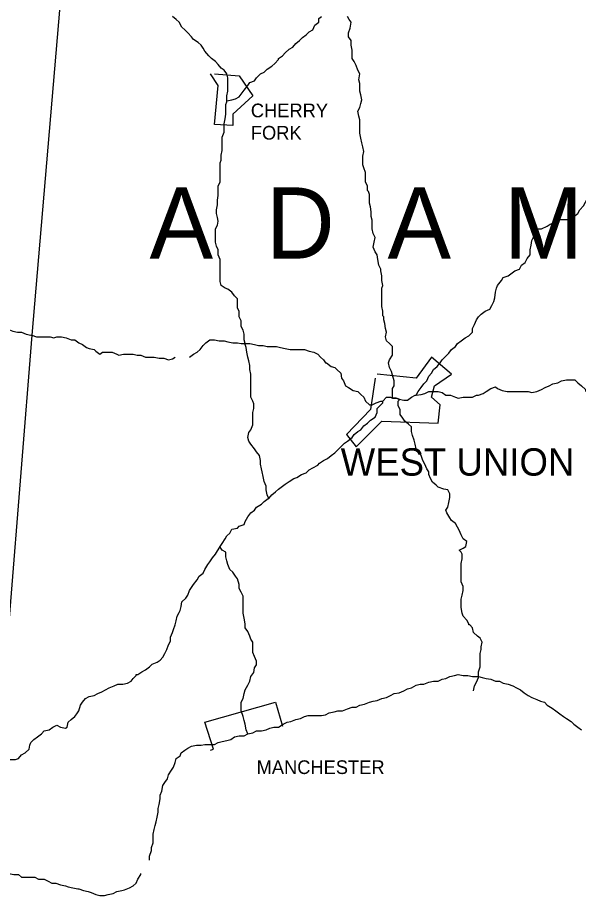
# Model space of a CAD drawing. Extents: x 0 to 40.2, y 0 to 22.
# Drawn here: x 3.548 to 4.348, y 15.986 to 17.238 of the extents above; entities that cross this region are included whole.
import ezdxf

# ---------------------------------------------------------------- set-up
doc = ezdxf.new("R2010")
doc.units = 0
doc.layers.add('Default', color=7, linetype='Continuous')
doc.layers.add('TR_Turning_Path1', color=7, linetype='Continuous')

msp = doc.modelspace()

# ---------------------------------------------------------------- linework, layer by layer
at = {"layer": 'Default'}
for points in [[(3.6488, 17.7215), (3.6215, 17.4107), (3.5684, 16.7848), (3.5206, 16.1972), (3.5111, 16.0241), (3.5097, 16.0009)], [(3.8465, 17.1189), (3.8465, 17.1257), (3.8479, 17.1325), (3.8479, 17.138), (3.8479, 17.1448), (3.8479, 17.1516), (3.8465, 17.1571), (3.8424, 17.1625), (3.8383, 17.1652), (3.8342, 17.1707), (3.8301, 17.1748), (3.8247, 17.1789), (3.8206, 17.183), (3.8151, 17.1898), (3.8124, 17.1939), (3.8097, 17.198), (3.8056, 17.2021), (3.7988, 17.2061), (3.796, 17.2102), (3.7906, 17.2157), (3.7865, 17.2198), (3.7824, 17.2239), (3.7783, 17.2307), (3.7742, 17.2348), (3.7688, 17.2389)], [(3.9201, 17.1789), (3.9256, 17.183), (3.9297, 17.1871), (3.9351, 17.1925), (3.9406, 17.1952), (3.9447, 17.2007), (3.9501, 17.2048), (3.9542, 17.2089), (3.9597, 17.213), (3.9638, 17.2171), (3.9692, 17.2198), (3.9719, 17.2266), (3.9774, 17.2307), (3.9774, 17.2361), (3.9815, 17.2389)], [(4.036, 17.0916), (4.0346, 17.0971), (4.0333, 17.1039), (4.036, 17.1093), (4.0374, 17.1148), (4.0387, 17.1202), (4.0374, 17.1271), (4.036, 17.1325), (4.036, 17.138), (4.036, 17.1434), (4.0346, 17.1489), (4.036, 17.1571), (4.0333, 17.1625), (4.0306, 17.1693), (4.0278, 17.1748), (4.0251, 17.1789), (4.0251, 17.1857), (4.0251, 17.1911), (4.0237, 17.198), (4.0237, 17.2048), (4.0197, 17.2102), (4.0197, 17.2157), (4.0224, 17.2225), (4.0237, 17.2307), (4.021, 17.2348), (4.0183, 17.2389)], [(3.8465, 17.1189), (3.8533, 17.1202), (3.8588, 17.1216), (3.8642, 17.1243), (3.8669, 17.1284), (3.871, 17.1339), (3.8765, 17.1407), (3.8792, 17.1448), (3.886, 17.1475), (3.8888, 17.1516), (3.8942, 17.1571), (3.8997, 17.1598), (3.9038, 17.1639), (3.9106, 17.168), (3.9147, 17.1721), (3.9201, 17.1775), (3.9201, 17.1789)], [(3.8288, 17.1571), (3.8642, 17.1543), (3.8833, 17.1257), (3.8547, 17.0998), (3.8547, 17.0834), (3.8288, 17.0848), (3.8342, 17.1407), (3.8233, 17.1571)], [(3.8301, 16.9362), (3.8329, 16.9416), (3.8342, 16.9471), (3.8329, 16.9525), (3.8315, 16.958), (3.8315, 16.9635), (3.8329, 16.9703), (3.8329, 16.9771), (3.8342, 16.9839), (3.8342, 16.9907), (3.8342, 16.9975), (3.837, 17.003), (3.837, 17.0098), (3.837, 17.0166), (3.837, 17.0234), (3.837, 17.0303), (3.8383, 17.0344), (3.8383, 17.0412), (3.8397, 17.048), (3.8397, 17.0548), (3.8397, 17.0603), (3.8397, 17.0671), (3.8424, 17.0739), (3.8424, 17.0807), (3.8424, 17.0862), (3.8438, 17.093), (3.8451, 17.0998), (3.8451, 17.1052), (3.8451, 17.1134), (3.8465, 17.1175), (3.8465, 17.1189)], [(4.0469, 16.9907), (4.0469, 16.9975), (4.0442, 17.003), (4.0442, 17.0098), (4.0442, 17.0166), (4.0415, 17.0234), (4.0401, 17.0275), (4.0401, 17.0344), (4.0401, 17.0398), (4.0415, 17.0466), (4.0401, 17.0534), (4.0387, 17.0589), (4.0374, 17.0657), (4.036, 17.0725), (4.036, 17.078), (4.036, 17.0848), (4.036, 17.0903), (4.036, 17.0903), (4.036, 17.0916)], [(4.3114, 16.9444), (4.3182, 16.9485), (4.3223, 16.9498), (4.3305, 16.9498), (4.336, 16.9498), (4.3414, 16.9539), (4.3469, 16.958), (4.3496, 16.9635), (4.3551, 16.9689), (4.3578, 16.9744), (4.3605, 16.9798), (4.3632, 16.9853), (4.3687, 16.9894), (4.3728, 16.9934), (4.3769, 16.9989), (4.3796, 17.0057), (4.3837, 17.0098), (4.3878, 17.0153), (4.3919, 17.0207), (4.3919, 17.0248)], [(4.066, 16.8789), (4.0633, 16.8844), (4.0619, 16.8926), (4.0606, 16.8994), (4.0578, 16.9035), (4.0551, 16.9103), (4.0565, 16.9171), (4.0578, 16.9239), (4.0551, 16.9294), (4.0537, 16.9362), (4.0537, 16.9416), (4.0537, 16.9485), (4.0524, 16.9539), (4.0524, 16.9607), (4.051, 16.9675), (4.0496, 16.973), (4.0496, 16.9798), (4.0496, 16.9853), (4.0483, 16.9894), (4.0469, 16.9907)], [(3.8724, 16.7726), (3.871, 16.778), (3.871, 16.7862), (3.8697, 16.7917), (3.8669, 16.7971), (3.8669, 16.8053), (3.8642, 16.8108), (3.8642, 16.8189), (3.8615, 16.823), (3.8615, 16.8298), (3.8615, 16.8367), (3.8574, 16.8407), (3.8533, 16.8462), (3.8479, 16.8503), (3.8438, 16.8517), (3.8383, 16.8557), (3.837, 16.8612), (3.837, 16.868), (3.837, 16.8748), (3.837, 16.8803), (3.837, 16.8871), (3.837, 16.8926), (3.8342, 16.8994), (3.8342, 16.9062), (3.8315, 16.9116), (3.8301, 16.9171), (3.8301, 16.9239), (3.8301, 16.9307), (3.8301, 16.9348), (3.8301, 16.9362)], [(4.2787, 16.9062), (4.2801, 16.913), (4.2814, 16.9198), (4.2842, 16.9253), (4.2869, 16.9307), (4.2896, 16.9362), (4.2951, 16.9362), (4.3032, 16.9403), (4.3073, 16.943), (4.3114, 16.9444), (4.3114, 16.9444)], [(4.2146, 16.8189), (4.2214, 16.8217), (4.2242, 16.8271), (4.2269, 16.8326), (4.2283, 16.838), (4.2296, 16.8462), (4.231, 16.8517), (4.2323, 16.8557), (4.2378, 16.8626), (4.2405, 16.8667), (4.2473, 16.8694), (4.2514, 16.8721), (4.2569, 16.8762), (4.2637, 16.8789), (4.2664, 16.8844), (4.2719, 16.8885), (4.2746, 16.8939), (4.2787, 16.8994), (4.2787, 16.9048), (4.2787, 16.9062), (4.2787, 16.9062)], [(4.0687, 16.8121), (4.0687, 16.8189), (4.0674, 16.8257), (4.0674, 16.8326), (4.0674, 16.838), (4.0674, 16.8435), (4.0674, 16.8517), (4.0687, 16.8557), (4.0674, 16.8626), (4.0674, 16.8694), (4.066, 16.8762), (4.066, 16.8789), (4.066, 16.8789)], [(3.4797, 16.8135), (3.4866, 16.8094), (3.4934, 16.8067), (3.4988, 16.8026), (3.5043, 16.8026), (3.5097, 16.7998), (3.5165, 16.7971), (3.522, 16.7958), (3.5288, 16.7944), (3.5343, 16.793), (3.5411, 16.7903), (3.5479, 16.7889), (3.5534, 16.7889), (3.5602, 16.7862), (3.567, 16.7848), (3.5684, 16.7848)], [(4.0824, 16.6949), (4.0824, 16.7017), (4.0824, 16.7085), (4.0851, 16.7126), (4.0851, 16.7194), (4.0824, 16.7276), (4.081, 16.733), (4.0783, 16.7385), (4.0769, 16.7453), (4.0783, 16.7494), (4.0824, 16.7562), (4.0824, 16.7617), (4.0824, 16.7685), (4.0783, 16.7726), (4.0742, 16.7767), (4.0728, 16.7821), (4.0742, 16.7889), (4.0728, 16.7944), (4.0715, 16.8012), (4.0701, 16.8067), (4.0701, 16.8108), (4.0687, 16.8121)], [(4.1165, 16.699), (4.1192, 16.7044), (4.1233, 16.7099), (4.1274, 16.7153), (4.1315, 16.7194), (4.1342, 16.7262), (4.1383, 16.7303), (4.141, 16.7358), (4.1464, 16.7399), (4.1505, 16.7453), (4.1533, 16.7494), (4.1574, 16.7535), (4.1628, 16.7589), (4.1669, 16.7644), (4.1724, 16.7685), (4.1751, 16.7726), (4.1805, 16.7767), (4.186, 16.7808), (4.1914, 16.7835), (4.1969, 16.7889), (4.1969, 16.7944), (4.1996, 16.7998), (4.2023, 16.8067), (4.2051, 16.8108), (4.2092, 16.8148), (4.2146, 16.8189), (4.2146, 16.8189), (4.2146, 16.8189)], [(3.5684, 16.7848), (3.5752, 16.7821), (3.5806, 16.7821), (3.5874, 16.7821), (3.5943, 16.7821), (3.5997, 16.7808), (3.6038, 16.7821), (3.6106, 16.7821), (3.6174, 16.7808), (3.6243, 16.778), (3.6297, 16.778), (3.6352, 16.7739), (3.6406, 16.7712), (3.6461, 16.7671), (3.6502, 16.7658), (3.657, 16.7644), (3.6597, 16.7617), (3.6652, 16.7576), (3.6693, 16.7603), (3.6761, 16.7603), (3.6829, 16.7603), (3.6897, 16.7576), (3.6924, 16.7562)], [(3.7933, 16.7535), (3.7988, 16.7576), (3.8042, 16.7603), (3.8083, 16.7644), (3.8124, 16.7698), (3.8165, 16.7739), (3.822, 16.778), (3.8288, 16.778), (3.8356, 16.7767), (3.8424, 16.7767), (3.8479, 16.7753), (3.8547, 16.7739), (3.8615, 16.7739), (3.8669, 16.7726), (3.871, 16.7726), (3.8724, 16.7726)], [(3.8833, 16.6662), (3.8833, 16.6744), (3.8847, 16.6799), (3.8847, 16.6867), (3.8833, 16.6908), (3.8806, 16.6962), (3.8806, 16.7044), (3.8806, 16.7099), (3.8806, 16.7167), (3.8806, 16.7235), (3.8806, 16.7289), (3.8792, 16.7358), (3.8792, 16.7412), (3.8779, 16.748), (3.8765, 16.7535), (3.8751, 16.7603), (3.8738, 16.7671), (3.8724, 16.7712), (3.8724, 16.7726)], [(3.8724, 16.7726), (3.8792, 16.7726), (3.886, 16.7712), (3.8915, 16.7698), (3.8983, 16.7698), (3.9038, 16.7685), (3.9119, 16.7685), (3.9174, 16.7685), (3.9228, 16.7671), (3.9297, 16.7658), (3.9365, 16.7644), (3.9433, 16.7644), (3.9501, 16.7644), (3.9569, 16.7644), (3.9569, 16.7644)], [(3.9569, 16.7644), (3.9638, 16.7617), (3.9706, 16.7603), (3.976, 16.7576), (3.9801, 16.7535), (3.9842, 16.7494), (3.9869, 16.7453), (3.9883, 16.7453)], [(3.6924, 16.7562), (3.6992, 16.7576), (3.7061, 16.7576), (3.7129, 16.7576), (3.7183, 16.7562), (3.7238, 16.7562), (3.7306, 16.7535), (3.7388, 16.7535), (3.7429, 16.7535), (3.7497, 16.7521), (3.7565, 16.7521), (3.7633, 16.7494), (3.7688, 16.7508), (3.7729, 16.7535), (3.7729, 16.7535)], [(4.0578, 16.7235), (4.051, 16.6785), (4.0169, 16.6431), (4.0306, 16.6253), (4.0674, 16.6621), (4.1478, 16.6594), (4.1505, 16.6853), (4.1383, 16.6962), (4.1424, 16.7126), (4.1669, 16.7289), (4.1383, 16.7535), (4.1165, 16.7235), (4.0606, 16.7289)], [(3.9883, 16.7453), (3.9951, 16.7399), (4.0006, 16.7385), (4.0033, 16.7358), (4.0087, 16.7303), (4.0101, 16.7235), (4.0128, 16.7194), (4.0156, 16.7126), (4.0197, 16.7099), (4.0265, 16.7058), (4.0333, 16.7044), (4.0374, 16.7003), (4.0415, 16.6962), (4.0442, 16.6908), (4.0496, 16.6853), (4.0537, 16.6853), (4.0592, 16.688), (4.066, 16.6908), (4.0687, 16.6908)], [(4.2051, 16.699), (4.2119, 16.7017), (4.216, 16.7044), (4.2228, 16.7085), (4.2296, 16.7112), (4.2323, 16.7085), (4.2392, 16.7058), (4.246, 16.7044), (4.2514, 16.7044), (4.2569, 16.7044)], [(4.2569, 16.7044), (4.2623, 16.7044), (4.2705, 16.7044), (4.276, 16.7044), (4.2814, 16.703), (4.2882, 16.7044), (4.2951, 16.7071), (4.3005, 16.7099), (4.306, 16.7126), (4.3114, 16.7153), (4.3182, 16.7167), (4.3237, 16.7194), (4.3305, 16.7208), (4.3373, 16.7208), (4.3428, 16.7208), (4.3469, 16.7167), (4.3523, 16.7126), (4.3578, 16.7071), (4.3578, 16.7044)], [(4.0919, 16.6935), (4.0987, 16.6921), (4.1042, 16.6921), (4.1096, 16.6962), (4.1151, 16.699), (4.1165, 16.699)], [(4.0919, 16.6935), (4.0987, 16.6921), (4.1042, 16.6921), (4.1096, 16.6962), (4.1151, 16.699), (4.1165, 16.699)], [(4.1165, 16.699), (4.1233, 16.7003), (4.1287, 16.7017), (4.1342, 16.7044), (4.141, 16.7044), (4.1478, 16.7044), (4.1533, 16.703), (4.1587, 16.699), (4.1655, 16.699), (4.1724, 16.6962), (4.1764, 16.6949), (4.1833, 16.6962), (4.1901, 16.6962), (4.1969, 16.6962), (4.2023, 16.699), (4.2051, 16.699), (4.2051, 16.699)], [(3.9065, 16.5517), (3.9106, 16.5572), (3.916, 16.5612), (3.9201, 16.5653), (3.9256, 16.5694), (3.9297, 16.5722), (3.9351, 16.5762), (3.9419, 16.5803), (3.946, 16.5817), (3.9528, 16.5858), (3.9597, 16.5885), (3.9638, 16.5926), (3.9692, 16.5953), (3.976, 16.5994), (3.9787, 16.6021), (3.9842, 16.6062), (3.9897, 16.609), (3.9951, 16.6131), (4.0006, 16.6171), (4.0047, 16.6212), (4.0087, 16.6253), (4.0142, 16.6308), (4.0183, 16.6335), (4.0251, 16.639), (4.0278, 16.6431), (4.0333, 16.6471), (4.0374, 16.6499), (4.0415, 16.6553), (4.0469, 16.6594), (4.051, 16.6635), (4.0578, 16.6676), (4.0606, 16.6744), (4.0606, 16.6799), (4.0646, 16.684), (4.0687, 16.688), (4.0687, 16.6908), (4.0687, 16.6908)], [(4.0687, 16.6908), (4.0742, 16.6962), (4.0796, 16.6962), (4.0824, 16.6949)], [(4.0687, 16.6908), (4.0742, 16.6962), (4.0796, 16.6962), (4.0824, 16.6949)], [(4.0824, 16.6949), (4.0878, 16.6949), (4.0919, 16.6935)], [(4.0824, 16.6949), (4.0878, 16.6949), (4.0919, 16.6935)], [(4.0919, 16.6935), (4.0878, 16.6949), (4.0824, 16.6949)], [(4.1342, 16.5899), (4.1315, 16.594), (4.1287, 16.6008), (4.126, 16.6062), (4.1233, 16.6131), (4.1192, 16.6171), (4.1165, 16.6226), (4.1151, 16.6294), (4.1137, 16.6349), (4.111, 16.6417), (4.1096, 16.6471), (4.1096, 16.654), (4.1055, 16.658), (4.1001, 16.6621), (4.0974, 16.6662), (4.0933, 16.6717), (4.0933, 16.6785), (4.0905, 16.684), (4.0905, 16.6908), (4.0919, 16.6921), (4.0919, 16.6935)], [(3.9065, 16.5517), (3.9038, 16.5572), (3.9024, 16.564), (3.9024, 16.5694), (3.8997, 16.5762), (3.8983, 16.5831), (3.8969, 16.5899), (3.8956, 16.594), (3.8942, 16.6008), (3.8942, 16.6062), (3.8929, 16.6131), (3.8888, 16.6185), (3.886, 16.6226), (3.8806, 16.6294), (3.8779, 16.6335), (3.8765, 16.639), (3.8779, 16.6458), (3.8806, 16.6499), (3.8833, 16.6567), (3.8833, 16.6621), (3.8833, 16.6662), (3.8833, 16.6662)], [(4.1778, 16.4781), (4.1833, 16.4808), (4.1874, 16.4835), (4.1887, 16.4903), (4.1833, 16.4944), (4.1805, 16.4999), (4.1778, 16.5067), (4.1751, 16.5108), (4.1724, 16.5163), (4.1669, 16.5203), (4.1642, 16.5244), (4.1601, 16.5312), (4.1587, 16.5353), (4.1614, 16.5394), (4.1628, 16.5462), (4.1642, 16.5531), (4.1642, 16.5585), (4.1614, 16.564), (4.156, 16.5653), (4.1478, 16.5681), (4.1451, 16.5708), (4.1396, 16.5749), (4.1369, 16.5803), (4.1342, 16.5858), (4.1342, 16.5899), (4.1342, 16.5899), (4.1342, 16.5899)], [(3.837, 16.4835), (3.8397, 16.4876), (3.8438, 16.4944), (3.8465, 16.4985), (3.8506, 16.5026), (3.8533, 16.5081), (3.8615, 16.5094), (3.8642, 16.5122), (3.871, 16.5149), (3.8724, 16.519), (3.8765, 16.5258), (3.8806, 16.5312), (3.886, 16.5353), (3.8888, 16.5394), (3.8956, 16.5435), (3.8997, 16.5476), (3.9051, 16.5517), (3.9065, 16.5517)], [(3.837, 16.4835), (3.8397, 16.4876), (3.8438, 16.4944), (3.8465, 16.4985), (3.8506, 16.5026), (3.8533, 16.5081), (3.8615, 16.5094), (3.8642, 16.5122), (3.871, 16.5149), (3.8724, 16.519), (3.8765, 16.5258), (3.8806, 16.5312), (3.886, 16.5353), (3.8888, 16.5394), (3.8956, 16.5435), (3.8997, 16.5476), (3.9051, 16.5517), (3.9065, 16.5517)], [(3.7797, 16.3922), (3.7811, 16.3976), (3.7824, 16.4045), (3.7879, 16.4099), (3.7906, 16.414), (3.7933, 16.4208), (3.796, 16.4249), (3.7988, 16.429), (3.8042, 16.4358), (3.807, 16.4413), (3.8124, 16.4454), (3.8151, 16.4508), (3.8192, 16.4576), (3.822, 16.4617), (3.826, 16.4672), (3.8301, 16.4726), (3.837, 16.4835)], [(3.8765, 16.2163), (3.8738, 16.2218), (3.8724, 16.2299), (3.871, 16.2354), (3.8697, 16.2408), (3.8669, 16.249), (3.8669, 16.2545), (3.8669, 16.2613), (3.8697, 16.2667), (3.871, 16.2736), (3.8724, 16.279), (3.8765, 16.2858), (3.8792, 16.2913), (3.8806, 16.2981), (3.8847, 16.3036), (3.886, 16.3104), (3.8888, 16.3145), (3.8888, 16.3199), (3.886, 16.3267), (3.8833, 16.3322), (3.8833, 16.339), (3.8833, 16.3472), (3.8806, 16.3513), (3.8792, 16.3554), (3.8765, 16.3622), (3.8724, 16.3676), (3.8724, 16.3731), (3.871, 16.3813), (3.8697, 16.3881), (3.8697, 16.3922), (3.8697, 16.399), (3.8697, 16.4058), (3.8697, 16.4126), (3.8669, 16.4181), (3.8642, 16.4235), (3.8642, 16.429), (3.8615, 16.4372), (3.8588, 16.4413), (3.8547, 16.4467), (3.8506, 16.4508), (3.8479, 16.4576), (3.8465, 16.4631), (3.8451, 16.4685), (3.8451, 16.4753), (3.8397, 16.4781), (3.837, 16.4822), (3.837, 16.4835)], [(4.1833, 16.4208), (4.1833, 16.4263), (4.1805, 16.4331), (4.1805, 16.4372), (4.1805, 16.4426), (4.1805, 16.4467), (4.1805, 16.4535), (4.1805, 16.459), (4.1819, 16.4658), (4.1819, 16.4726), (4.1805, 16.4753), (4.1778, 16.4781)], [(4.1914, 16.3731), (4.1887, 16.3785), (4.1833, 16.384), (4.1819, 16.3881), (4.1805, 16.3963), (4.1805, 16.4017), (4.1805, 16.4085), (4.1819, 16.414), (4.1833, 16.4208), (4.1833, 16.4208)], [(3.7197, 16.3008), (3.7252, 16.3049), (3.7306, 16.3076), (3.7361, 16.3117), (3.7401, 16.3158), (3.747, 16.3186), (3.7511, 16.3213), (3.7551, 16.3254), (3.7579, 16.3308), (3.7606, 16.3363), (3.7633, 16.3431), (3.7661, 16.3486), (3.7661, 16.354), (3.7688, 16.3608), (3.7701, 16.3649), (3.7729, 16.3717), (3.7742, 16.3772), (3.7756, 16.384), (3.7783, 16.3895), (3.7797, 16.3922), (3.7797, 16.3922)], [(4.2051, 16.2981), (4.2051, 16.3049), (4.2078, 16.3117), (4.2078, 16.3172), (4.2078, 16.3226), (4.2078, 16.3308), (4.2092, 16.3363), (4.2092, 16.3404), (4.2105, 16.3472), (4.2078, 16.3526), (4.2037, 16.3554), (4.1983, 16.3608), (4.1969, 16.3676), (4.1928, 16.3717), (4.1914, 16.3717), (4.1914, 16.3731)], [(3.6188, 16.2258), (3.6202, 16.2327), (3.6243, 16.2368), (3.6297, 16.2408), (3.6324, 16.2449), (3.6352, 16.249), (3.6379, 16.2572), (3.6406, 16.2613), (3.6447, 16.2667), (3.6502, 16.2695), (3.657, 16.2708), (3.6624, 16.2736), (3.6679, 16.2763), (3.6733, 16.279), (3.6788, 16.2817), (3.6856, 16.2845), (3.6911, 16.2872), (3.6979, 16.2872), (3.7047, 16.2886), (3.7102, 16.2913), (3.7129, 16.2954), (3.717, 16.2995), (3.717, 16.3008), (3.7197, 16.3008)], [(3.8765, 16.2163), (3.8833, 16.2177), (3.8888, 16.2204), (3.8956, 16.2204), (3.9024, 16.2218), (3.9078, 16.2245), (3.9133, 16.2258), (3.9201, 16.2258), (3.9269, 16.2299), (3.9324, 16.2327), (3.9378, 16.234), (3.9447, 16.2368), (3.9515, 16.2381), (3.9569, 16.2408), (3.9624, 16.2422), (3.9678, 16.2422), (3.976, 16.2422), (3.9815, 16.2422), (3.9869, 16.2436), (3.9924, 16.2463), (3.9992, 16.2477), (4.0047, 16.249), (4.0115, 16.249), (4.0183, 16.2517), (4.0251, 16.2545), (4.0306, 16.2545), (4.036, 16.2572), (4.0428, 16.2586), (4.0496, 16.2613), (4.0551, 16.2627), (4.0606, 16.264), (4.0674, 16.2667), (4.0742, 16.2681), (4.0796, 16.2708), (4.0851, 16.2736), (4.0919, 16.2749), (4.0987, 16.2777), (4.1042, 16.2804), (4.1096, 16.2817), (4.1165, 16.2858), (4.1219, 16.2872), (4.1274, 16.2872), (4.1342, 16.2899), (4.141, 16.2913), (4.1478, 16.2913), (4.1533, 16.294), (4.1587, 16.2954), (4.1642, 16.2981), (4.171, 16.2995), (4.1764, 16.3008), (4.1833, 16.2995), (4.1901, 16.2995), (4.1969, 16.2981), (4.2023, 16.2981), (4.2037, 16.2981), (4.2051, 16.2981)], [(4.1983, 16.2777), (4.1996, 16.2845), (4.2023, 16.2899), (4.2051, 16.2967), (4.2051, 16.2981)], [(4.2051, 16.2981), (4.2105, 16.2967), (4.216, 16.2954), (4.2228, 16.294), (4.2296, 16.2913), (4.2351, 16.2913), (4.2405, 16.2886), (4.2473, 16.2872), (4.2542, 16.2845), (4.2596, 16.2817), (4.2651, 16.279), (4.2705, 16.2749), (4.276, 16.2708), (4.2814, 16.2681), (4.2882, 16.2654), (4.2937, 16.2627), (4.2992, 16.2613), (4.3032, 16.2572), (4.3101, 16.2531), (4.3155, 16.249), (4.321, 16.2449), (4.3264, 16.2408), (4.3305, 16.2381), (4.3373, 16.234), (4.3414, 16.2299), (4.3469, 16.2258), (4.3523, 16.2218)], [(3.8233, 16.1931), (3.8274, 16.1945), (3.8151, 16.2327), (3.916, 16.2613), (3.9256, 16.2272)], [(3.5206, 16.1972), (3.5206, 16.189), (3.5206, 16.1836), (3.5261, 16.1809), (3.5329, 16.1795), (3.5397, 16.1795), (3.5452, 16.1795), (3.5493, 16.1809), (3.5534, 16.1863), (3.5588, 16.189), (3.5643, 16.1945), (3.5656, 16.1999), (3.567, 16.204), (3.5711, 16.2081), (3.5765, 16.2122), (3.582, 16.2163), (3.5861, 16.2204), (3.5929, 16.2218), (3.5984, 16.2258), (3.6038, 16.2286), (3.6093, 16.2258), (3.6161, 16.2245), (3.6188, 16.2258), (3.6188, 16.2258)], [(3.7811, 16.189), (3.7865, 16.1931), (3.7906, 16.1958), (3.796, 16.1986), (3.8029, 16.1999), (3.8097, 16.1999), (3.8151, 16.2013), (3.822, 16.2013), (3.8288, 16.2013), (3.8342, 16.204), (3.8397, 16.2054), (3.8465, 16.2068), (3.8519, 16.2081), (3.8574, 16.2122), (3.8642, 16.2136), (3.871, 16.2136), (3.8765, 16.2163), (3.8765, 16.2163)], [(3.7361, 16.0363), (3.7361, 16.0418), (3.7388, 16.05), (3.7388, 16.0541), (3.7415, 16.0609), (3.7415, 16.0663), (3.7415, 16.0731), (3.7429, 16.08), (3.7442, 16.0854), (3.7456, 16.0909), (3.747, 16.0977), (3.7483, 16.1045), (3.7483, 16.11), (3.7497, 16.1154), (3.7511, 16.1236), (3.7511, 16.129), (3.7538, 16.1345), (3.7551, 16.1427), (3.7579, 16.1468), (3.762, 16.1522), (3.7633, 16.1577), (3.7674, 16.1645), (3.7701, 16.1686), (3.7729, 16.1754), (3.7742, 16.1809), (3.7797, 16.1849), (3.7811, 16.189), (3.7811, 16.189)], [(3.5111, 16.0241), (3.5179, 16.0227), (3.5234, 16.02), (3.5288, 16.0186), (3.5356, 16.0172), (3.5425, 16.0159), (3.5493, 16.0159), (3.5534, 16.0118), (3.5602, 16.0118), (3.567, 16.0118), (3.5724, 16.0118), (3.5779, 16.0091), (3.5861, 16.0091), (3.5915, 16.0063), (3.597, 16.0036), (3.6024, 16.0036), (3.6093, 16.0009), (3.6161, 15.9995), (3.6202, 15.9982), (3.627, 15.9968), (3.6338, 15.9954), (3.6352, 15.9954), (3.6352, 15.9954)], [(3.6352, 15.9954), (3.642, 15.9927), (3.6488, 15.9913), (3.6529, 15.99), (3.6597, 15.9872), (3.6652, 15.9859), (3.672, 15.9859), (3.6774, 15.9872), (3.6842, 15.9886), (3.6897, 15.9913), (3.6965, 15.9927), (3.7006, 15.9941), (3.7074, 15.9968), (3.7129, 15.9995), (3.717, 16.0036), (3.7197, 16.0091), (3.7238, 16.0159), (3.7238, 16.0159), (3.7238, 16.0172)]]:
    msp.add_lwpolyline(points, dxfattribs=at)

# ---------------------------------------------------------------- texts
for s, height, p in [('CHERRY', 0.0195, (3.8806, 17.0953)), ('FORK', 0.0195, (3.8806, 17.0635)), ('WEST UNION', 0.039, (4.0087, 16.5844)), ('MANCHESTER', 0.0195, (3.8888, 16.159))]:
    msp.add_text(s, height=height, dxfattribs=at).set_placement(p)
at = {"layer": 'TR_Turning_Path1'}
msp.add_text('A  D  A  M  S', height=0.101489, dxfattribs=at).set_placement((3.7362, 16.8939))

doc.saveas('drawing.dxf')
